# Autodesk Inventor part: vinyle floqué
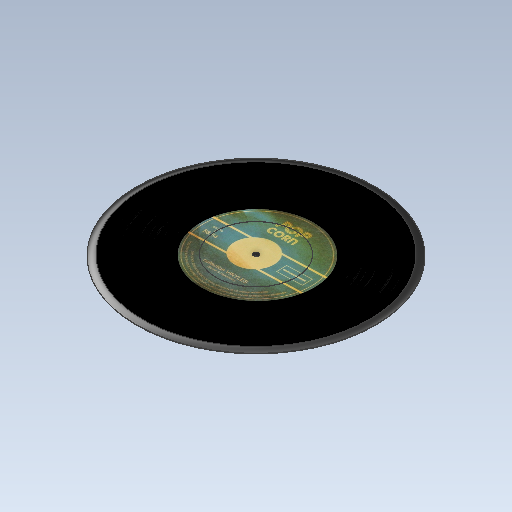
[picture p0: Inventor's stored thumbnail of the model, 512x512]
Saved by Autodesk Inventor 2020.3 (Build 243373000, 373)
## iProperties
Created: 2020-09
Part Number: vinyle floqué
Material: Plastique PAEK
Document SubType Name: Modeling
Designer: ficho
Density: 1.32 g/cm^3
Appearance: Lustré - Noir
Mass: 358.054 g
Surface Area: 1425.33 cm^2
Volume: 271.253 cm^3
Author: ficho
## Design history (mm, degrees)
sketch "Esquisse1"
  geometry: L1 (50.294, 0)-(141.99, 0); L2 (149.99, 1.67)-(149.99, 2.33); L3 (141.99, 4)-(50.294, 4); L4 (3.5, 3.8)-(3.5, 0.2); L5 (0, -23.201)-(0, 27.2) reference; L6 (3.5, 3.8)-(50.294, 3.8); L7 (50.294, 3.8)-(50.294, 4); L8 (3.5, 0.2)-(50.294, 0.2); L9 (50.294, 0.2)-(50.294, 0); A1 r 20 centre (141.99, 20) between (141.99, 0) and (149.99, 1.67); A2 r 20.001 centre (141.99, -16.001) between (149.99, 2.33) and (141.99, 4); 1 further point
  constraints: 16 end point, 4 point on circle, 2 centre point, 2 parallel, 2 tangent, 1 horizontal, 1 perpendicular
  dimensions: "d1" = 4 distance between parallel lines of L1 L3; "d2" = 3.5 distance from line of L4 point (0, 0); "d4" = 8 distance from line of A1.centre L2; "d5" = 8 distance from line of A2.centre L2 (= d4); "d6" = 40 diameter of A1; "d9" = 0.2 distance between parallel lines of L1 L8
revolve "Révolution1" sketch "Esquisse1" stored, may be unused: angle "d3" = 90 deg
node "Point de construction1"
sketch "Esquisse3"
  geometry: L1 (-180, 150)-(180, 150); L2 (180, 150)-(180, -150); L3 (180, -150)-(-180, -150); L4 (-180, -150)-(-180, 150); 1 further point; 1 other entity
  constraints: 2 other
  dimensions: "d23" = 150 vertical distance of point (0, 0) L1.start
feature "Décalcomanie1" sketch "Esquisse3"
sketch "Esquisse4"
  geometry: L1 (-183.755, 150)-(176.245, 150); L2 (176.245, 150)-(176.245, -150); L3 (176.245, -150)-(-183.755, -150); L4 (-183.755, -150)-(-183.755, 150); 1 further point; 1 other entity
  constraints: 2 other
  dimensions: "d31" = 360 distance between parallel lines of L2 L4; "d35" = 150 vertical distance of point (0, 0) L1.start
feature "Décalcomanie2" sketch "Esquisse4"
node "Solide1"
node "Image1"
node "Image2"
